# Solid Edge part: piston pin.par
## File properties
Author: Robert a Rhodes jr
Template: Normal.par
Last saved by: CADCIM
Revision: 7
Application: Solid Edge
Accuracy: 0.99
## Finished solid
Body 1: solid body, 4 faces, 4 edges, 0 vertices.
  Faces by surface: cylinder 2, plane 2
  Edges by curve: circle 4
Bounding box of the edges (mm): 22.000 x 22.000 x 80.000, from (-11, -11, -80) to (11, 11, 0).
Cylindrical faces by radius (mm): R5.5 x1, R11 x1
Planar faces by outward normal: +z 1, -z 1
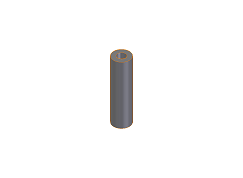
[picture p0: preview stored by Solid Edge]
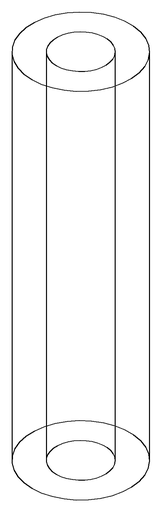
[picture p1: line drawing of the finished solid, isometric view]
